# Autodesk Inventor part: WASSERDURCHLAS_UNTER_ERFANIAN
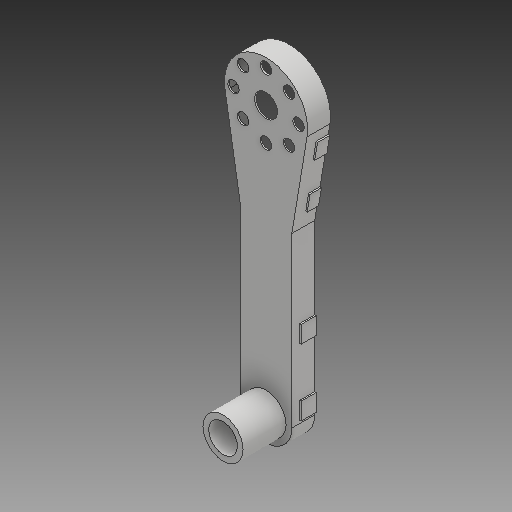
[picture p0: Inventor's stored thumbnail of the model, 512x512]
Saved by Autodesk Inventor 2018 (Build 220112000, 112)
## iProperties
Created: 2019-01
Part Number: WASSERDURCHLAS_UNTER_ERFANIAN
Material: Generisch
Document SubType Name: Modeling
Designer: zand
Density: 1 g/cm^3
Appearance: Vorgabe
Author: zand
Revision Number: 16LAST_VERSION
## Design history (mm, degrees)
feature "Basis1"
node "Volumenkörper1"
